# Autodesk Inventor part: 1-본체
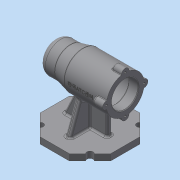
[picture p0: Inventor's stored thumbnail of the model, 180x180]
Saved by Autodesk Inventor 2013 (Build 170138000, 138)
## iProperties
Created: 2019-12
Part Number: 1-본체
Material: 일반
Document SubType Name: Modeling
Designer: Administrator
Density: 1 g/cm^3
Author: Administrator
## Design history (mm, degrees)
sketch "스케치1" dims "d0" = 112
  geometry: L1 (23.196, 56)-(56, 23.196); L2 (56, 23.196)-(56, -23.196); L3 (56, -23.196)-(23.196, -56); L4 (23.196, -56)-(-23.196, -56); L5 (-23.196, -56)-(-56, -23.196); L6 (-56, -23.196)-(-56, 23.196); L7 (-56, 23.196)-(-23.196, 56); L8 (-23.196, 56)-(23.196, 56); C1 r 5 at (-39.598, 39.598); C2 r 5 at (-39.598, -39.598); C3 r 5 at (39.598, -39.598); C4 r 5 at (39.598, 39.598); 4 further points
  constraints: 16 end point, 5 midpoint, 4 centre point, 3 equal radius, 2 coincident, 2 vertical alignment, 19 other
  dimensions: "d2" = 10 diameter of C1
extrude "돌출1" new body sketch "스케치1" distance "d3" = 10; taper "d4" = 0 deg
extrude "돌출2" cut sketch "스케치1" distance "d5" = 10; taper "d6" = 0 deg
sketch "스케치2"
  geometry: L1 (-56, 80)-(56, 80); L2 (56, 101)-(41, 101); L3 (41, 101)-(41, 104); L4 (41, 104)-(-13, 104); L5 (-13, 104)-(-13, 101); L6 (-13, 101)-(-25, 101); L7 (-25, 101)-(-25, 97.5); L8 (-25, 97.5)-(-43, 97.5); L9 (-43, 97.5)-(-43, 96); L10 (-43, 96)-(-47, 96); L11 (-47, 96)-(-47, 90.5); L12 (-47, 90.5)-(-50, 90.5); L13 (-50, 90.5)-(-50, 80); L14 (-56, 80)-(-56, 105); L15 (-56, 105)-(-31, 105); L16 (-31, 105)-(-11, 110); L17 (-11, 110)-(56, 110); L18 (56, 110)-(56, 101); 2 further points
  constraints: 36 end point, 12 parallel, 2 horizontal, 2 perpendicular, 2 vertical alignment, 1 collinear, 1 point on line
  dimensions: "d7" = 112 distance of L1.start L1.end; "d9" = 80 distance from line of L1 point (0, 0); "d10" = 15 distance of L2.start L2.end; "d11" = 54 distance of L3.end L4.end; "d12" = 3 distance of L11.end L12.end; "d13" = 4 distance of L9.end L10.end; "d14" = 12 distance of L5.end L6.end; "d15" = 18 distance of L7.end L8.end; "d16" = 25 distance from line of L15.end L14; "d17" = 45 distance from line of L16.end L14; "d19" = 42 diameter of L2 L1; "d20" = 48 diameter of L4 L1; "d21" = 42 diameter of L6 L1; "d22" = 21 diameter of L12 L1; "d23" = 32 diameter of L10 L1; "d24" = 35 diameter of L8 L1; "d25" = 60 diameter of L17 L1; "d26" = 50 diameter of L15 L1
revolve "회전1" sketch "스케치2" stored, may be unused: angle "d27" = 90 deg
sketch "스케치3"
  geometry: C1 r 21 at (0, 0) reference; C2 r 6 at (0, -30); 2 further points
  constraints: 2 vertical alignment, 1 centre point, 1 other
  dimensions: "d28" = 12 diameter of C2
extrude "돌출3" join sketch "스케치3" distance "d30" = 16; taper "d31" = 0 deg
sketch "스케치4"
  geometry: A1 r 6 centre (0, 0) between (-5.97, 0.6) and (5.97, 0.6) reference; 2 further points
  constraints: 1 coincident
hole "구멍1" sketch "스케치4" at (0, 0) diameter "d32" = 3.242; stored, may be unused: countersink angle "d36" = 90 deg, drill point angle "d38" = 118 deg; dims "d33" = 8, "d34" = 4, "d35" = 2, "d37" = 11
sketch "스케치5"
  geometry: L1 (23.196, 56)-(-23.196, 56) reference; L2 (-4, 0)-(4, 0); L3 (4, 0)-(4, 31); L4 (4, 31)-(-4, 31); L5 (-4, 31)-(-4, 0); 2 further points
  constraints: 8 end point, 2 midpoint, 2 parallel, 1 horizontal, 1 perpendicular, 1 vertical alignment
  dimensions: "d42" = 8 distance of L3.end L4.end; "d44" = 25 distance between parallel lines of L4 L1
extrude "돌출4" join sketch "스케치5" stored distance "d45" = 16; taper "d46" = 0 deg
sketch "스케치6"
  geometry: L1 (-31, 55)-(-11, 50) reference; L2 (-11, 50)-(40, 50) reference; L3 (-23.196, 10)-(-36.062, 10) reference; L4 (23.196, 10)-(-23.196, 10) reference; L5 (-43.134, 10)-(-34.598, 10) reference; L6 (-43.134, 10)-(-56, 10) reference; L7 (-18.476, 51.869)-(-38, 10); 1 further point
  constraints: 2 end point, 2 point on line
  dimensions: "d47" = 18 distance of L7.end L6.end; "d48" = 115 deg angle of L7 L6
feature "리브1" sketch "스케치6" dims "d49" = 1, "d50" = 8, "d51" = 0, "d52" = 0, "d53" = 1, "d54" = 1
sketch "스케치7"
  geometry: L1 (23.196, 10)-(-23.196, 10) reference; L2 (36.062, 10)-(23.196, 10) reference; L3 (34.598, 10)-(43.134, 10) reference; L4 (-23.196, 10)-(-36.062, 10) reference; L5 (-43.134, 10)-(-34.598, 10) reference; L6 (-43.134, 10)-(-56, 10) reference; L7 (56, 10)-(43.134, 10) reference; L8 (18.979, 56.766)-(36, 10); A1 r 30 centre (0, 80) between (4, 50.268) and (-4, 50.268) reference; 1 further point
  constraints: 2 end point, 1 point on circle, 1 point on line
  dimensions: "d55" = 20 distance of L8.end L7.start; "d56" = 110 deg angle of L3 L8
feature "리브2" sketch "스케치7" dims "d57" = 1, "d58" = 8, "d59" = 0, "d60" = 0, "d61" = 1, "d62" = 1
node "작업 평면1"
sketch "스케치8"
  geometry: L1 (33.5, 5.97)-(33.5, 29.4) reference; L2 (17.5, 6)-(17.5, -6) reference; 5 further points
  constraints: 1 horizontal alignment, 1 midpoint, 1 other
  dimensions: "d63" = 41 distance from line of point (-7.5, 0) L1
feature "엠보싱1" sketch "스케치8" dims "d64" = 0.5, "d65" = 0
fillet "모깎기1" dims "d66" = 0.3
fillet "모깎기2" dims "d67" = 1, "d68" = 3
fillet "모깎기4" dims "d70" = 3
fillet "모깎기5" dims "d71" = 3
fillet "모깎기6" dims "d72" = 3
fillet "모깎기7" dims "d73" = 3
chamfer "모따기1" distance "d74" = 1; stored, may be unused: second distance "d75" = 2, angle "d76" = 45 deg
fillet "모깎기8" dims "d77" = 3
fillet "모깎기9" dims "d78" = 10
node "솔리드1"
pattern_circular "원형 패턴1" dims angle "d40" = 360 deg
mirror "대칭1"
